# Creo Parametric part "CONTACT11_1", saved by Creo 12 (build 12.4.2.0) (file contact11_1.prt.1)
Units: Custom; MM, KILOGRAM, SECS

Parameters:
  PTC_WM_ITERATION = "0"
  PTC_WM_VERSION = "-.0"
  PTC_WM_LIFECYCLE_STATE = "In Work"
  PTC_WM_LIFECYCLE = "MO_CADDocument"
  PTC_WM_CREATED_BY = "Maximilian Roepper (Z0017RMS: MO)"
  PTC_WM_CREATED_ON = "18-Sep-26 11:36:42 AM"
  PTC_WM_MODIFIED_BY = "Maximilian Roepper (Z0017RMS: MO)"
  PTC_WM_MODIFIED_ON = "18-Sep-26 11:36:46 AM"
  PDMLINKNUMBER = "PDM000071455177"
  PTC_WM_NAME = "contact11_1.prt"
  PTC_WM_NUMBER = "PDM000071455177"

Other parameters: WEIGHT, WEIGHT_FACTOR, WEIGHT_ADD, _MASS_TEMP, _DIFF_TEMP, MC_ERRORS, SUPPLIER

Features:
  1. coordinate system
  2. datum plane "PRT_YZ"
  3. datum plane "PRT_XY"
  4. datum plane "PRT_XZ"
  5. coordinate system
  6. datum axis
  7. datum axis
  8. datum axis
  9. coordinate system
  10. imported feature

Other named items: PRT, SIEMENS_MO, DRW_VIEW_ORG, PRT_X, PRT_Y, PRT_Z, CS0, ROUGH_GROB

Layers: 00_STD_CSYS-KSYS, 01_STD_PLANES-EBENEN, 02_STD_AXES-ACHSEN, 03_STD_CSYS-KSYS, 24_IMPORT_FEAT-IMPORT_KE

Surfaces: 20 plane, 2 cylinder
